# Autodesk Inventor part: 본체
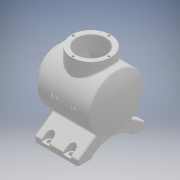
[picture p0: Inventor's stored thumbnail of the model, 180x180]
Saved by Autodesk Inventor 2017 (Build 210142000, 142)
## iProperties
Part Number: 본체
Material: 일반
Document SubType Name: Modeling
Designer: MRC
Density: 1 g/cm^3
Appearance: 기본값
Author: MRC
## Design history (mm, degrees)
sketch "스케치2"
  geometry: L1 (0, 0)-(0, 36); L2 (0, 36)-(12, 36); L3 (12, 36)-(12, 50); L4 (12, 50)-(108.336, 50); L5 (120, 0)-(0, 0); A1 r 113 centre (7, 0) between (120, 0) and (108.336, 50)
  constraints: 10 end point, 3 perpendicular, 2 point on circle, 1 centre point, 1 horizontal, 1 point on line, 1 vertical
  dimensions: "d0" = 113 radius of A1; "d1" = 72 diameter of L2 L5; "d2" = 100 diameter of L4 L5; "d3" = 120 distance of L5.start L1.start; "d4" = 108 distance from line of L5.start L3
revolve "회전1" sketch "스케치2" stored, may be unused: angle "d5" = 90 deg
node "작업 평면1"
sketch "스케치3"
  geometry: C1 r 36 at (62, 0); 1 further point
  constraints: 1 centre point, 1 horizontal alignment
  dimensions: "d7" = 72 diameter of C1; "d8" = 62 distance of point (0, 0) C1.centre
extrude "돌출1" join sketch "스케치3" stored distance "d9" = 10; taper "d10" = 0 deg
sketch "스케치4"
  geometry: L1 (0, 0)-(0, 27); L2 (0, 27)-(-19, 27); L3 (-19, 27)-(-19, 43); L4 (-19, 43)-(-103.887, 43); L5 (0, 0)-(-113, 0); A1 r 106 centre (-7, 0) between (-103.887, 43) and (-113, 0)
  constraints: 10 end point, 3 perpendicular, 2 point on circle, 1 centre point, 1 horizontal, 1 point on line, 1 vertical
  dimensions: "d12" = 19 distance of L1.end L2.end; "d13" = 54 diameter of L2 L5; "d14" = 86 diameter of L4 L5; "d15" = 106 radius of A1; "d16" = 113 distance of L1.start L5.end
revolve "회전2" sketch "스케치4" stored, may be unused: angle "d17" = 90 deg
sketch "스케치5"
  geometry: C1 r 36 at (0, 0) reference; C2 r 27 at (0, 0); 1 further point
  constraints: 1 centre point, 1 coincident
  dimensions: "d18" = 54 diameter of C2
extrude "돌출2" cut sketch "스케치5" stored distance "d19" = 10; taper "d20" = 0 deg
node "작업 평면2"
sketch "스케치6"
  geometry: L1 (26.694, -42.278)-(62, -67); L2 (62, -67)-(62, -77); L3 (62, -77)-(38.5, -77); L4 (-38.5, -77)-(-62, -77); L5 (-62, -77)-(-62, -67); L6 (-62, -67)-(-26.694, -42.278); L7 (0, 0)-(-50, 0); L8 (0, 0)-(0, 50); L9 (0, -112.096)-(0, -60); A1 r 52.096 centre (0, -112.096) between (38.5, -77) and (-38.5, -77); A2 r 50 centre (0, 0) between (26.694, -42.278) and (-26.694, -42.278) reference
  constraints: 18 end point, 7 point on circle, 3 vertical, 2 horizontal, 2 perpendicular, 1 centre point, 1 collinear, 1 symmetric about line, 1 vertical alignment, 1 other
  dimensions: "d22" = 10 distance of L1.end L2.end; "d23" = 10 distance of L4.end L5.end; "d24" = 77 distance of L4.start L3.end; "d25" = 17 distance from line of L4 L9.end; "d26" = 55 deg angle of L5 L6; "d27" = 77 distance between parallel lines of L7 L4; "d28" = 124 distance between parallel lines of L5 L2
extrude "돌출3" join sketch "스케치6" distance "d29" = 80; taper "d30" = 0 deg
sketch "스케치7"
  geometry: L1 (0, 0)-(-80, 0) reference; L2 (0, 0)-(0, 23.5) reference; 5 further points
  constraints: 2 horizontal alignment, 2 vertical alignment
  dimensions: "d31" = 108 distance of point (-20, 8) point (-20, 116); "d32" = 8 distance from line of L1 point (-20, 8); "d33" = 40 distance of point (-60, 8) point (-20, 8); "d34" = 20 distance from line of L2 point (-20, 8)
hole "구멍1" sketch "스케치7" at (-20, 116), (-20, 8), (-60, 116), (-60, 8) diameter "d35" = 9; stored, may be unused: countersink angle "d39" = 90 deg, drill point angle "d41" = 0 deg; dims "d36" = 6, "d37" = 4, "d38" = 2, "d40" = 6
sketch "스케치8"
  geometry: L1 (7, -8)-(7, 0); L2 (20, -8)-(-60, -8) reference; L3 (-7, 0)-(-7, -8); C1 r 4.5 at (0, 0) reference; A1 r 7 centre (0, 0) between (7, 0) and (-7, 0); 1 further point
  constraints: 4 end point, 4 point on circle, 4 point on line, 2 tangent, 2 vertical, 1 centre point, 1 coincident
  dimensions: "d42" = 14 diameter of A1
extrude "돌출4" cut sketch "스케치8" stored distance "d43" = 80; taper "d44" = 0 deg
node "작업 평면3"
sketch "스케치9"
  geometry: L1 (0, 0)-(0, 27); 2 further points
  constraints: 2 end point, 1 horizontal alignment, 1 vertical, 1 vertical alignment, 1 other
  dimensions: "d47" = 32.5 distance from line of L1 point (-32.5, 0)
hole "구멍2" sketch "스케치9" at (-32.5, 0) diameter "d48" = 3.242; stored, may be unused: countersink angle "d52" = 90 deg, drill point angle "d54" = 118 deg; dims "d49" = 8, "d50" = 4, "d51" = 2, "d53" = 10
sketch "스케치10"
  geometry: 2 further points
  constraints: 1 horizontal alignment
  dimensions: "d58" = 32.5 distance of point (0, 0) point (32.5, 0)
hole "구멍3" sketch "스케치10" at (32.5, 0) diameter "d59" = 3.242; stored, may be unused: countersink angle "d63" = 90 deg, drill point angle "d65" = 118 deg; dims "d60" = 8, "d61" = 4, "d62" = 2, "d64" = 10
chamfer "모따기1" distance "d69" = 1; stored, may be unused: second distance "d70" = 2, angle "d71" = 45 deg
fillet "모깎기1" dims "d72" = 3
fillet "모깎기2" dims "d73" = 3
fillet "모깎기3" dims "d74" = 3
fillet "모깎기4" dims "d75" = 3
fillet "모깎기5" dims "d76" = 3
node "작업 평면4"
sketch "스케치11"
  geometry: L1 (0, -36)-(0, 36) reference; 3 further points
  constraints: 1 horizontal alignment, 1 midpoint, 1 other
  dimensions: "d78" = 62 distance from line of L1 point (62, 0)
feature "엠보싱1" sketch "스케치11" dims "d0" = 113, "d1" = 72, "d2" = 100, "d3" = 120, "d4" = 108, "d15" = 106, "d79" = 0.5, "d80" = 0
node "솔리드1"
mirror "미러1"
mirror "미러2"
pattern_circular "원형 패턴1" dims angle "d56" = 360 deg
pattern_circular "원형 패턴2" dims angle "d67" = 360 deg
other parameters: "d6" = 65, "d77" = -94.25
